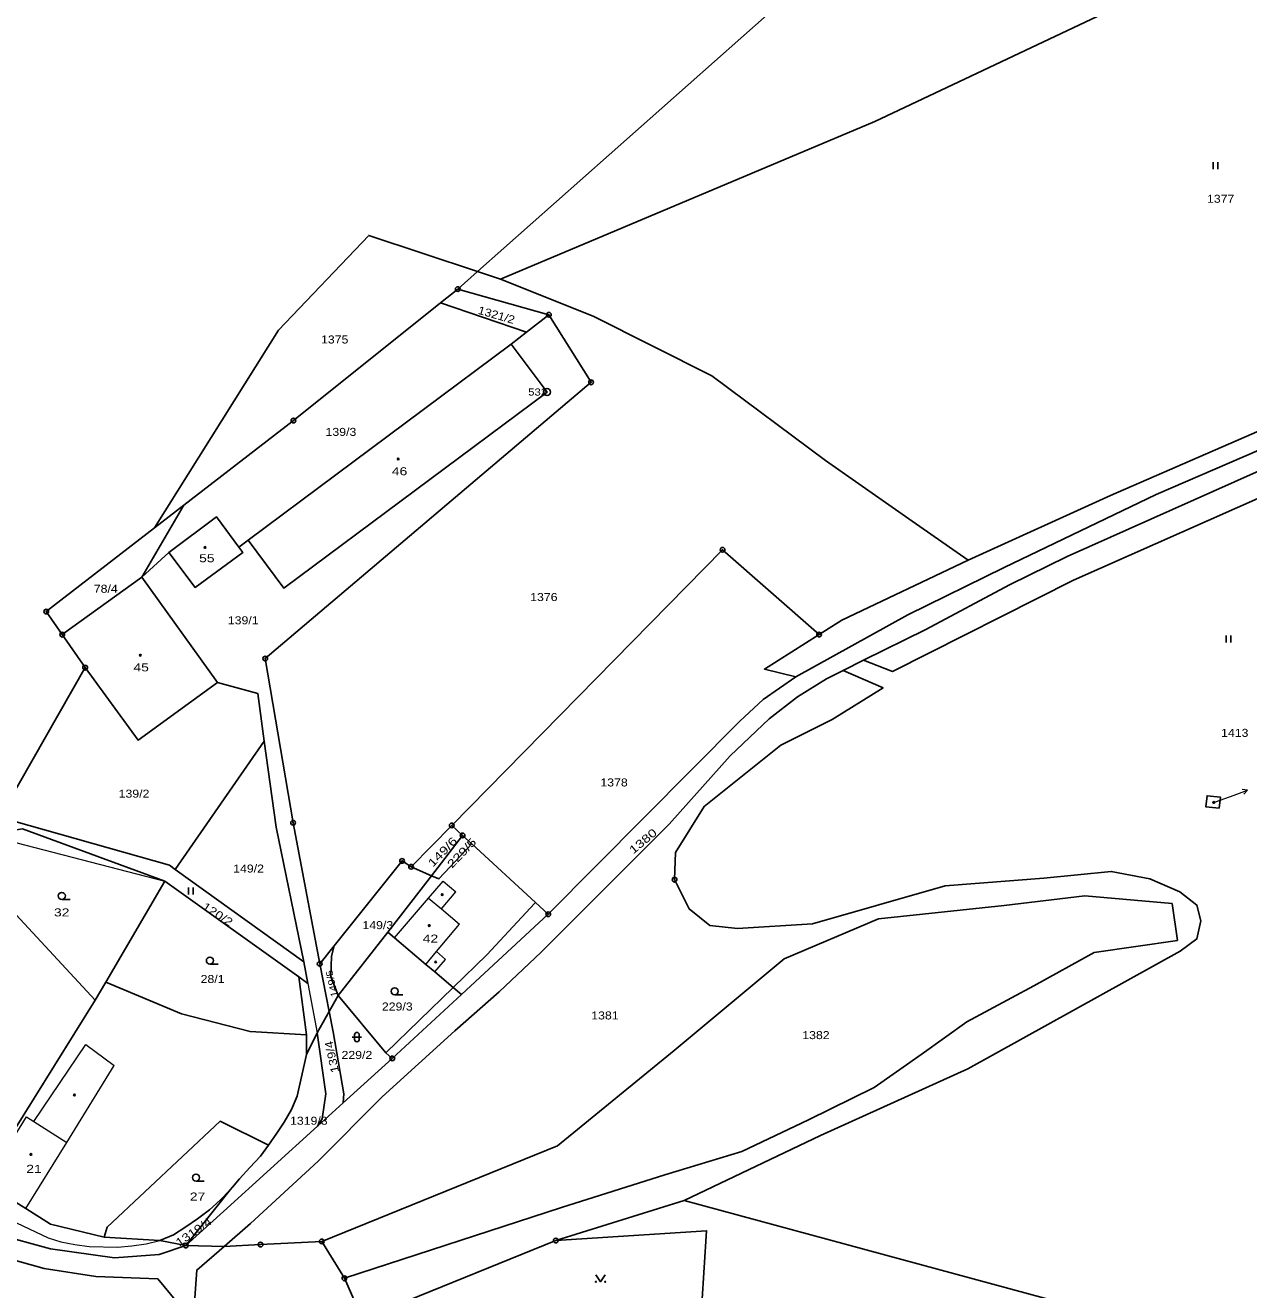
# Model space of a CAD drawing. Extents: x -872229 to -869198, y -1075981 to -1074329.
# Drawn here: x -870924.3 to -870664.3, y -1075205 to -1074936.4 of the extents above; entities that cross this region are included whole.
import ezdxf
from ezdxf.enums import TextEntityAlignment as Align

# ---------------------------------------------------------------- set-up
doc = ezdxf.new("R2010")
doc.units = 0
doc.header["$LTSCALE"] = 0.68
for name, color, linetype, lineweight in [('1', 7, 'Continuous', 25), ('3', 7, 'Continuous', 25), ('4', 7, 'Continuous', 13), ('5', 7, 'Continuous', 25), ('7', 7, 'Continuous', 13), ('8', 7, 'Continuous', 25)]:
    doc.layers.add(name, color=color, linetype=linetype, lineweight=lineweight)
doc.layers.add('2', color=7, linetype='Continuous')

msp = doc.modelspace()

# ---------------------------------------------------------------- linework, layer by layer
at = {"layer": '1'}
for p, q in [((-870832.43, -1074992.44), (-870828.23, -1074988.72)), ((-870828.23, -1074988.72), (-870823.34, -1074990.34)), ((-870832.43, -1074992.44), (-870813.05, -1074997.9)), ((-870817.8, -1075001.55), (-870836.08, -1074995.36)), ((-870821.1, -1075004.1), (-870876.96, -1075045.75)), ((-870890.62, -1075038.35), (-870899.54, -1075053.64)), ((-870896.85, -1075043.16), (-870890.62, -1075038.35)), ((-870876.96, -1075045.75), (-870878.94, -1075047.23)), ((-870893.79, -1075048.39), (-870899.54, -1075053.64)), ((-870916.45, -1075065.85), (-870911.59, -1075072.86)), ((-870837.98, -1075117.09), (-870831.39, -1075108.5)), ((-870892.44, -1075115.73), (-870865.1, -1075135.39)), ((-870837.98, -1075117.09), (-870842.32, -1075115.15)), ((-870857.82, -1075142.49), (-870847.25, -1075129.09)), ((-870858.7, -1075131.95), (-870861.76, -1075135.78)), ((-870907.21, -1075139.69), (-870909.44, -1075143.5)), ((-870857.82, -1075142.49), (-870859.76, -1075145.91)), ((-870856.75, -1075165.32), (-870846.32, -1075155.87)), ((-870862.22, -1075170.28), (-870856.75, -1075165.32)), ((-870784.32, -1075186.07), (-870610.3, -1075233.15)), ((-870907.54, -1075193.83), (-870895.75, -1075194.57)), ((-870895.75, -1075194.57), (-870890.21, -1075195.64)), ((-870890.21, -1075195.64), (-870882.08, -1075195.84)), ((-870856.49, -1075202.6), (-870861.31, -1075194.77))]:
    msp.add_line(p, q, dxfattribs=at)
for points in [[(-870828.23, -1074988.72), (-870733.1, -1074904.34), (-870634.05, -1074816.48)], [(-870823.34, -1074990.34), (-870743.76, -1074956.82), (-870646.76, -1074910.9), (-870624.12, -1074897.23)], [(-870723.96, -1075050), (-870693.71, -1075036.28), (-870649.55, -1075017.06), (-870584.14, -1074987.8), (-870552.32, -1074975.37), (-870546.15, -1074971.5), (-870542.19, -1074967.42)], [(-870896.85, -1075043.16), (-870870.5, -1075001.16), (-870851.34, -1074981.04), (-870828.23, -1074988.72)], [(-870760.55, -1075074.8), (-870736.8, -1075061.65), (-870716.28, -1075051.57), (-870684.01, -1075036.04), (-870643.52, -1075018.55), (-870612.61, -1075004.24), (-870591.23, -1074994.43), (-870570.04, -1074985.9), (-870558.3, -1074982.28), (-870544.73, -1074980.25)], [(-870746.19, -1075071.27), (-870732.98, -1075064.74), (-870715.15, -1075055.28), (-870702.93, -1075049.25), (-870662.75, -1075031.31), (-870646.95, -1075024.02), (-870627.8, -1075016.08), (-870598.46, -1075002.7), (-870582.08, -1074994.97), (-870575.53, -1074992.25), (-870561.97, -1074987.44), (-870555.39, -1074985.35), (-870547.72, -1074984.42), (-870543.16, -1074984.27), (-870536.54, -1074984.58), (-870532.83, -1074984.88), (-870528.68, -1074985.73), (-870515.43, -1074988.43), (-870489.43, -1074993.61), (-870451.62, -1074998.98)], [(-870723.96, -1075050), (-870735.85, -1075041.72), (-870754.24, -1075028.86), (-870778.4, -1075010.85), (-870803.61, -1074998.16), (-870823.34, -1074990.34)], [(-870890.62, -1075038.35), (-870867.33, -1075020.36), (-870836.08, -1074995.36), (-870832.43, -1074992.44)], [(-870861.76, -1075135.78), (-870867.42, -1075105.8), (-870873.32, -1075070.92), (-870804.09, -1075012.24), (-870813.05, -1074997.9), (-870817.8, -1075001.55), (-870821.1, -1075004.1)], [(-870876.96, -1075045.75), (-870869.36, -1075056), (-870813.44, -1075014.3), (-870821.1, -1075004.1)], [(-870746.19, -1075071.27), (-870740.01, -1075073.65), (-870701.56, -1075054.27), (-870661.14, -1075036.37), (-870626.13, -1075019.06), (-870610.36, -1075011.6)], [(-870916.45, -1075065.85), (-870919.85, -1075060.95), (-870896.85, -1075043.16)], [(-870878.94, -1075047.23), (-870883.7, -1075040.81), (-870893.79, -1075048.39)], [(-870893.79, -1075048.39), (-870888.25, -1075055.83), (-870878.08, -1075048.38), (-870878.94, -1075047.23)], [(-870833.7, -1075106.39), (-870776.15, -1075047.82), (-870755.65, -1075065.84)], [(-870755.65, -1075065.84), (-870750.79, -1075062.78), (-870723.96, -1075050)], [(-870911.59, -1075072.86), (-870900.34, -1075088.23), (-870883.44, -1075076.03), (-870899.54, -1075053.64), (-870916.45, -1075065.85)], [(-870760.55, -1075074.8), (-870767.27, -1075073.18), (-870755.65, -1075065.84)], [(-870882.08, -1075195.84), (-870876.48, -1075190.98), (-870862.11, -1075177.7), (-870848.46, -1075164.05), (-870833.06, -1075150.02), (-870823.61, -1075141.72), (-870814.66, -1075133.34), (-870787.51, -1075106.14), (-870774.51, -1075091.61), (-870766.24, -1075083.76), (-870760.23, -1075079.03), (-870754.08, -1075075.24), (-870750.53, -1075073.45), (-870746.19, -1075071.27)], [(-870930.06, -1075104.56), (-870928.47, -1075102.44), (-870911.59, -1075072.86)], [(-870813.18, -1075125.26), (-870772.47, -1075084.22), (-870767.49, -1075079.65), (-870760.55, -1075074.8)], [(-870784.32, -1075186.07), (-870755.33, -1075172.29), (-870724.06, -1075158.07), (-870678.88, -1075133.11), (-870675.36, -1075130.49), (-870674.52, -1075126.66), (-870675.34, -1075123.32), (-870678.97, -1075120.49), (-870685.35, -1075117.73), (-870693.57, -1075116.15), (-870707.89, -1075117.61), (-870728.84, -1075119.23), (-870757.05, -1075127.29), (-870772.94, -1075128.29), (-870778.87, -1075127.61), (-870783.25, -1075124.12), (-870786.34, -1075117.9), (-870786.18, -1075112.16), (-870780.09, -1075102.34), (-870763.77, -1075089.36), (-870752.86, -1075083.85), (-870742.03, -1075077.18), (-870750.53, -1075073.45)], [(-870883.44, -1075076.03), (-870874.9, -1075078.35), (-870873.52, -1075088.47)], [(-870930.06, -1075104.56), (-870893.7, -1075114.82), (-870892.44, -1075115.73), (-870873.52, -1075088.47)], [(-870873.52, -1075088.47), (-870871.03, -1075106.76), (-870865.1, -1075135.39)], [(-870894.66, -1075118.2), (-870924.88, -1075107.13), (-870932.92, -1075108.35)], [(-870858.7, -1075131.95), (-870844.26, -1075113.92), (-870842.32, -1075115.15), (-870833.7, -1075106.39)], [(-870833.7, -1075106.39), (-870831.39, -1075108.5), (-870829.44, -1075110.29)], [(-870829.44, -1075110.29), (-870836.42, -1075117.76), (-870837.98, -1075117.09)], [(-870829.44, -1075110.29), (-870815.89, -1075122.76), (-870813.18, -1075125.26)], [(-870864.56, -1075150.9), (-870866.19, -1075138.58), (-870894.66, -1075118.2), (-870907.21, -1075139.69)], [(-870837.98, -1075117.09), (-870847.25, -1075129.09), (-870845.84, -1075130.29)], [(-870909.44, -1075143.5), (-870927.17, -1075124.39), (-870932.72, -1075121.96), (-870936.66, -1075131.14), (-870945.89, -1075145.67), (-870949.71, -1075143.97), (-870951.3, -1075148.19), (-870958.37, -1075166.98), (-870949.29, -1075170.31), (-870949.89, -1075171.55)], [(-870861.31, -1075194.77), (-870811.22, -1075174.45), (-870786.41, -1075154.2), (-870763.05, -1075134.75), (-870742.98, -1075126.21), (-870716.31, -1075123.38), (-870699.19, -1075121.37), (-870680.62, -1075122.97), (-870679.5, -1075130.81), (-870697.18, -1075133.41), (-870710, -1075140.48), (-870724.25, -1075148.13), (-870733.72, -1075154.9), (-870743.9, -1075162.08), (-870757.91, -1075168.9), (-870772.04, -1075175.68), (-870788.41, -1075180.62), (-870810.37, -1075187.53), (-870856.49, -1075202.6)], [(-870813.18, -1075125.26), (-870831.64, -1075142.31), (-870846.32, -1075155.87)], [(-870845.84, -1075130.29), (-870839.22, -1075135.9), (-870837.31, -1075137.51), (-870833.4, -1075140.82), (-870831.64, -1075142.31)], [(-870857.82, -1075142.49), (-870859.36, -1075138.42), (-870859.25, -1075134.15), (-870858.7, -1075131.95)], [(-870865.1, -1075135.39), (-870864.25, -1075139.97), (-870866.19, -1075138.58)], [(-870864.56, -1075150.9), (-870864.55, -1075155.07), (-870862.32, -1075150.43), (-870859.76, -1075145.91), (-870861.76, -1075135.78)], [(-870907.21, -1075139.69), (-870891.11, -1075146.44), (-870876.55, -1075150.17), (-870864.56, -1075150.9)], [(-870846.32, -1075155.87), (-870847.68, -1075154.69), (-870857.82, -1075142.49)], [(-870949.89, -1075171.55), (-870931.15, -1075178.18), (-870909.44, -1075143.5)], [(-870856.75, -1075165.32), (-870856.65, -1075163.41), (-870858.9, -1075150.23), (-870859.76, -1075145.91)], [(-870862.32, -1075150.43), (-870860.42, -1075163.37), (-870861.23, -1075168.69), (-870862.22, -1075170.28)], [(-870890.21, -1075195.64), (-870895.9, -1075197.55), (-870905.34, -1075198.25), (-870918.98, -1075196.32), (-870930.4, -1075193.2), (-870939.76, -1075189.14), (-870966.78, -1075174.22), (-871004.43, -1075162.38), (-871023.49, -1075157.84), (-871022.7, -1075155.06)], [(-870864.55, -1075155.07), (-870866.56, -1075163.88), (-870867.75, -1075166.75), (-870869.33, -1075169.39), (-870870.88, -1075171.78), (-870872.64, -1075174.34)], [(-870907.54, -1075193.83), (-870906.89, -1075191.76), (-870882.9, -1075169.23), (-870872.64, -1075174.34)], [(-870890.21, -1075195.64), (-870882.21, -1075188.39), (-870862.22, -1075170.28)], [(-870872.64, -1075174.34), (-870874.32, -1075176.63), (-870876.57, -1075179.07), (-870878.78, -1075181.49), (-870880.31, -1075183.23), (-870880.8, -1075183.78), (-870890.21, -1075195.64)], [(-870931.15, -1075178.18), (-870930.37, -1075178.46), (-870932.82, -1075182.43), (-870924.17, -1075187.79)], [(-870880.8, -1075183.78), (-870882.93, -1075186.01), (-870885.17, -1075188.02), (-870887.7, -1075189.96), (-870890.19, -1075191.67), (-870892.85, -1075193.36), (-870895.75, -1075194.57)], [(-870924.17, -1075187.79), (-870918.98, -1075191.1), (-870907.54, -1075193.83)], [(-870852.61, -1075211.21), (-870811.58, -1075194.57), (-870784.32, -1075186.07)], [(-870811.58, -1075194.57), (-870779.53, -1075192.5), (-870781.56, -1075223.68)], [(-870882.08, -1075195.84), (-870887.87, -1075200.84), (-870890.54, -1075238.17)], [(-870861.31, -1075194.77), (-870874.33, -1075195.43), (-870882.08, -1075195.84)], [(-870925.85, -1075268.83), (-870908.47, -1075274.58), (-870898.66, -1075275.61), (-870893.76, -1075273.35), (-870892.7, -1075270.97), (-870894.88, -1075238.8), (-870892.1, -1075207.59), (-870896.18, -1075202.7), (-870909.34, -1075202.24), (-870920.27, -1075200.54), (-870931.8, -1075197.32)], [(-870852.61, -1075211.21), (-870854.23, -1075207.71), (-870856.49, -1075202.6)]]:
    msp.add_lwpolyline(points, dxfattribs=at)
msp.add_lwpolyline([(-870670.61, -1075102.74), (-870670.36, -1075100.35), (-870673.18, -1075100.06), (-870673.43, -1075102.45)], close=True, dxfattribs=at)
at = {"layer": '3'}
for p, q in [((-870671.891, -1074966.97), (-870671.891, -1074965.47)), ((-870670.89, -1074966.97), (-870670.89, -1074965.47)), ((-870669.151, -1075067.5), (-870669.151, -1075066)), ((-870668.15, -1075067.5), (-870668.15, -1075066)), ((-870889.631, -1075121.08), (-870889.631, -1075119.58)), ((-870888.63, -1075121.08), (-870888.63, -1075119.58)), ((-870916.553, -1075122.11), (-870914.803, -1075122.11)), ((-870885.093, -1075135.85), (-870883.343, -1075135.85)), ((-870845.823, -1075142.37), (-870844.073, -1075142.37)), ((-870854.861, -1075151.341), (-870852.859, -1075151.341)), ((-870854.361, -1075150.841), (-870854.361, -1075151.842)), ((-870853.359, -1075151.842), (-870853.359, -1075150.841)), ((-870888.033, -1075181.95), (-870886.283, -1075181.95))]:
    msp.add_line(p, q, dxfattribs=at)
msp.add_lwpolyline([(-870803.07, -1075201.839), (-870802.07, -1075203.34), (-870801.07, -1075201.839)], dxfattribs=at)
for centre, radius in [((-870916.5529, -1075121.3598), 0.75), ((-870885.0929, -1075135.0998), 0.75), ((-870845.8229, -1075141.6198), 0.75), ((-870888.0329, -1075181.1998), 0.75), ((-870803.07, -1075203.3395), 0.1), ((-870801.07, -1075203.3395), 0.1)]:
    msp.add_circle(centre, radius, dxfattribs=at)
for centre, start, end in [((-870853.86, -1075150.8409), 0, 180), ((-870853.86, -1075151.8409), 180, 359.98789)]:
    msp.add_arc(centre, 0.5, start, end, dxfattribs=at)
at = {"layer": '4'}
for p, q in [((-870932.92, -1075108.35), (-870894.66, -1075118.2)), ((-870838.61, -1075121.81), (-870835.53, -1075118.19)), ((-870835.53, -1075118.19), (-870832.84, -1075120.48)), ((-870835.87, -1075124.13), (-870832.84, -1075120.48)), ((-870845.84, -1075130.29), (-870838.61, -1075121.81)), ((-870838.61, -1075121.81), (-870835.87, -1075124.13)), ((-870816.01, -1075122.88), (-870815.89, -1075122.76)), ((-870835.87, -1075124.13), (-870832.06, -1075127.37)), ((-870836.91, -1075133.15), (-870832.06, -1075127.37)), ((-870839.22, -1075135.9), (-870836.91, -1075133.15)), ((-870836.91, -1075133.15), (-870835.03, -1075134.84)), ((-870837.31, -1075137.51), (-870835.03, -1075134.84)), ((-870864.25, -1075139.97), (-870862.32, -1075150.43)), ((-870847.68, -1075154.69), (-870833.4, -1075140.82)), ((-870922.52, -1075169.25), (-870911.46, -1075152.94)), ((-870911.46, -1075152.94), (-870905.41, -1075157.36)), ((-870915.47, -1075173.71), (-870905.41, -1075157.36)), ((-870930.37, -1075178.46), (-870924.07, -1075168.28)), ((-870924.17, -1075187.79), (-870915.47, -1075173.71)), ((-870936.12, -1075186.16), (-870919.45, -1075194.01)), ((-870919.45, -1075194.01), (-870916.78, -1075194.85)), ((-870916.78, -1075194.85), (-870913.82, -1075195.43)), ((-870913.82, -1075195.43), (-870910.76, -1075195.81)), ((-870910.76, -1075195.81), (-870904.71, -1075195.96)), ((-870898.65, -1075195.28), (-870895.75, -1075194.57))]:
    msp.add_line(p, q, dxfattribs=at)
for points in [[(-870833.4, -1075140.82), (-870826.26, -1075133.88), (-870816.01, -1075122.88)], [(-870924.07, -1075168.28), (-870922.52, -1075169.25), (-870915.47, -1075173.71)], [(-870904.71, -1075195.96), (-870901.65, -1075195.7), (-870898.65, -1075195.28)]]:
    msp.add_lwpolyline(points, dxfattribs=at)
at = {"layer": '5'}
for centre in [(-870845.0668, -1075028.5292), (-870886.1268, -1075047.3192), (-870899.8668, -1075070.2092), (-870671.7668, -1075101.4992), (-870835.7168, -1075121.0792), (-870838.4868, -1075127.6492), (-870837.0968, -1075135.3892), (-870913.8668, -1075163.6392), (-870923.1268, -1075176.2892)]:
    msp.add_circle(centre, 0.175, dxfattribs=at)
at = {"layer": '7'}
msp.add_line((-870664.6, -1075098.904), (-870665.712, -1075098.776), dxfattribs=at)
msp.add_lwpolyline([(-870671.43, -1075101.37), (-870667.42, -1075099.93), (-870664.6, -1075098.904), (-870665.37, -1075099.717)], dxfattribs=at)
at = {"layer": '8'}
for centre, radius in [((-870832.43, -1074992.4399), 0.5), ((-870832.43, -1074992.4399), 0.0303), ((-870813.05, -1074997.8999), 0.5), ((-870813.05, -1074997.8999), 0.0303), ((-870813.44, -1075014.2998), 0.75), ((-870804.09, -1075012.2399), 0.5), ((-870804.09, -1075012.2399), 0.0303), ((-870813.44, -1075014.2998), 0.03), ((-870867.33, -1075020.3599), 0.5), ((-870867.33, -1075020.3599), 0.0303), ((-870776.15, -1075047.8199), 0.5), ((-870776.15, -1075047.8199), 0.0303), ((-870919.85, -1075060.9499), 0.5), ((-870919.85, -1075060.9499), 0.0303), ((-870916.45, -1075065.8499), 0.5), ((-870916.45, -1075065.8499), 0.0303), ((-870755.65, -1075065.8399), 0.5), ((-870755.65, -1075065.8399), 0.0303), ((-870911.59, -1075072.8599), 0.5), ((-870873.32, -1075070.9199), 0.5), ((-870873.32, -1075070.9199), 0.0303), ((-870911.59, -1075072.8599), 0.0303), ((-870867.42, -1075105.7999), 0.5), ((-870867.42, -1075105.7999), 0.0303), ((-870833.7, -1075106.3899), 0.5), ((-870833.7, -1075106.3899), 0.0303), ((-870831.39, -1075108.4999), 0.5), ((-870831.39, -1075108.4999), 0.0303), ((-870844.26, -1075113.9199), 0.5), ((-870844.26, -1075113.9199), 0.0303), ((-870842.32, -1075115.1499), 0.5), ((-870842.32, -1075115.1499), 0.0303), ((-870786.34, -1075117.8999), 0.5), ((-870786.34, -1075117.8999), 0.0303), ((-870813.18, -1075125.2599), 0.5), ((-870813.18, -1075125.2599), 0.0303), ((-870861.76, -1075135.7799), 0.5), ((-870861.76, -1075135.7799), 0.0303), ((-870846.32, -1075155.8699), 0.5), ((-870846.32, -1075155.8699), 0.0303), ((-870890.21, -1075195.6399), 0.5), ((-870890.21, -1075195.6399), 0.0303), ((-870874.33, -1075195.4299), 0.5), ((-870874.33, -1075195.4299), 0.0303), ((-870861.31, -1075194.7699), 0.5), ((-870861.31, -1075194.7699), 0.0303), ((-870811.58, -1075194.5699), 0.5), ((-870811.58, -1075194.5699), 0.0303), ((-870856.49, -1075202.5999), 0.5), ((-870856.49, -1075202.5999), 0.0303)]:
    msp.add_circle(centre, radius, dxfattribs=at)

# ---------------------------------------------------------------- texts
at = {"layer": '2'}
for s, width, p in [('1377', 1.15, (-870673.21, -1074974.09)), ('1375', 1.15, (-870861.47, -1075003.99)), ('139/3', 1.15, (-870860.51, -1075023.62)), ('46', 1.3, (-870846.43, -1075031.98)), ('55', 1.3, (-870887.38, -1075050.46)), ('78/4', 1.15, (-870909.76, -1075056.95)), ('1376', 1.15, (-870817.03, -1075058.71)), ('139/1', 1.15, (-870881.28, -1075063.65)), ('45', 1.3, (-870901.34, -1075073.65)), ('1413', 1.15, (-870670.22, -1075087.56)), ('1378', 1.15, (-870802.11, -1075098.1)), ('139/2', 1.15, (-870904.48, -1075100.48)), ('149/2', 1.15, (-870880.14, -1075116.39)), ('32', 1.3, (-870918.22, -1075125.71)), ('149/3', 1.15, (-870852.68, -1075128.41)), ('42', 1.3, (-870839.86, -1075131.27)), ('28/1', 1.15, (-870887.06, -1075139.86)), ('229/3', 1.15, (-870848.54, -1075145.7)), ('1381', 1.15, (-870804.05, -1075147.6)), ('1382', 1.15, (-870759.21, -1075151.78)), ('229/2', 1.15, (-870857.12, -1075155.99)), ('1319/3', 1.15, (-870868.06, -1075169.97)), ('21', 1.3, (-870924.1, -1075180.19)), ('27', 1.3, (-870889.35, -1075186.07))]:
    msp.add_text(s, height=1.7, dxfattribs=dict(at, width=width)).set_placement(p)
for s, height, rotation, width, p in [('1321/2', 1.7, 344, 1.15, (-870828.274, -1074997.647)), ('1380', 1.7, 40, 1.35, (-870795.133, -1075112.571)), ('149/6', 1.7, 46, 1.35, (-870837.718, -1075115.35)), ('229/5', 1.7, 46, 1.35, (-870833.638, -1075115.59)), ('120/2', 1.7, 327, 1.25, (-870886.882, -1075124.012)), ('149/5', 1.445, 102, 1.2, (-870857.863, -1075142.699)), ('139/4', 1.7, 102, 1.2, (-870857.638, -1075158.733)), ('1319/4', 1.7, 35, 1.25, (-870891.612, -1075195.916))]:
    msp.add_text(s, height=height, rotation=rotation, dxfattribs=dict(at, width=width)).set_placement(p)
at = {"layer": '8', "width": 1.2}
msp.add_text('532', height=1.5, dxfattribs=at).set_placement((-870813.44, -1075015.05), align=Align.RIGHT)

doc.saveas('drawing.dxf')
